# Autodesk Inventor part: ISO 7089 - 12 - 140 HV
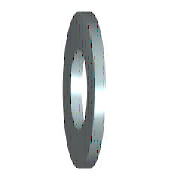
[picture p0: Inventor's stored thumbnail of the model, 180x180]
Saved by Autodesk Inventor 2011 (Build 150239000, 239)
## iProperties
IsCustomPart: 0
Created: 2009-02
Part Number: ISO 7089 - 12 - 140 HV
Material: Stainless Steel
Description: Plain washers - Normal series - Product grade A
Document SubType Name: Modeling
Standard: ISO 7089
Designer: V.de Jong
Standard Revision: Second edition 2000-06-01
Standards Organization: ISO
Language: en-US
Size Designation: 12 - 140 HV
Categories: <MemberInstance><Categories><Category DisplayName="Fasteners" InternalName="e4da775c-781d-43d5-af7c-5136215cf5a6" Mnemonic="FSTN"><Category DisplayName="Washers
Density: 8.08 g/cm^3
Mass: 6.45707 g
Surface Area: 9.29911 cm^2
Volume: 0.799143 cm^3
Author: V.de Jong
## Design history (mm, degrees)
body "Solid1"
sketch "Sketch"
  geometry: C1 r 12 at (0, 0); C2 r 6.5 at (0, 0); 1 further point
  constraints: 2 centre point, 2 coincident
  dimensions: "d0" = 13 diameter of C2 (= SD1); "d1" = 24 diameter of C1 (= SD2)
extrude "Body" new body sketch "Sketch" distance "d2" = 2.5 (= SD); taper "d3" = 0 deg
workaxis "Work Axis1"
workplane "Work Plane1"
other parameters: "SD1" = 13 [user parameter; used in 1 equation term], "SD2" = 24 [user parameter; used in 1 equation term], "SD" = 2.5 [user parameter; used in 1 equation term], "d4" = 0, "d5" = 0, "d6" = 0, "d7" = 0, "NND" = 12 [user parameter]
